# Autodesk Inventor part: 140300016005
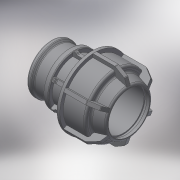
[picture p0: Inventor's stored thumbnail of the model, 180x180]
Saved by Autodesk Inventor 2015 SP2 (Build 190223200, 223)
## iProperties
Created: 2017-08
Part Number: 140300016005
Material: Generic
Description: PLASSON L.14 FEMALE ADAPTOR (SILVER) 16-1/2"
Document SubType Name: Modeling
Designer: KIM
Density: 1 g/cm^3
Appearance: Default
Author: KIM
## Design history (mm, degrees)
derived "140300.ipt"
feature "Solid1::140300.ipt"
tag "TaggingFeature1"
body "Solid1"
other parameters: "d1" = 16, "d2" = 55, "d4" = 15 deg, "d5" = 36.3, "d6" = 11.979, "d9" = 18.631, "d10" = 39, "d11" = 24.2203, "d12" = 22.3572, "d13" = 26.0834, "d14" = 19, "d16" = 16.32, "d17" = 2.75, "d18" = 77, "d19" = 5.7, "d20" = 135 deg, "d21" = 5.7, "d22" = 22.3572, "d23" = 14.4, "d24" = 2.75, "d25" = 35.1, "d26" = 29.25, "d27" = 2.75, "d28" = 135 deg, "d29" = 1.65, "d31" = 0.8, "d44" = 0.32, "d45" = 0.48, "d46" = 150 deg, "d49" = 1.95, "d50" = 0, "d51" = 0.39, "d52" = 0.78, "d53" = 45 deg, "d55" = 7.068, "d56" = 1.95, "d57" = 0, "d58" = 0.48, "d61" = 360 deg, "d_" = 16, "G_" = 18.631, "E_" = 39, "H_" = 77, "l_" = 55, "l_2" = 19, "d54" = 17.67
